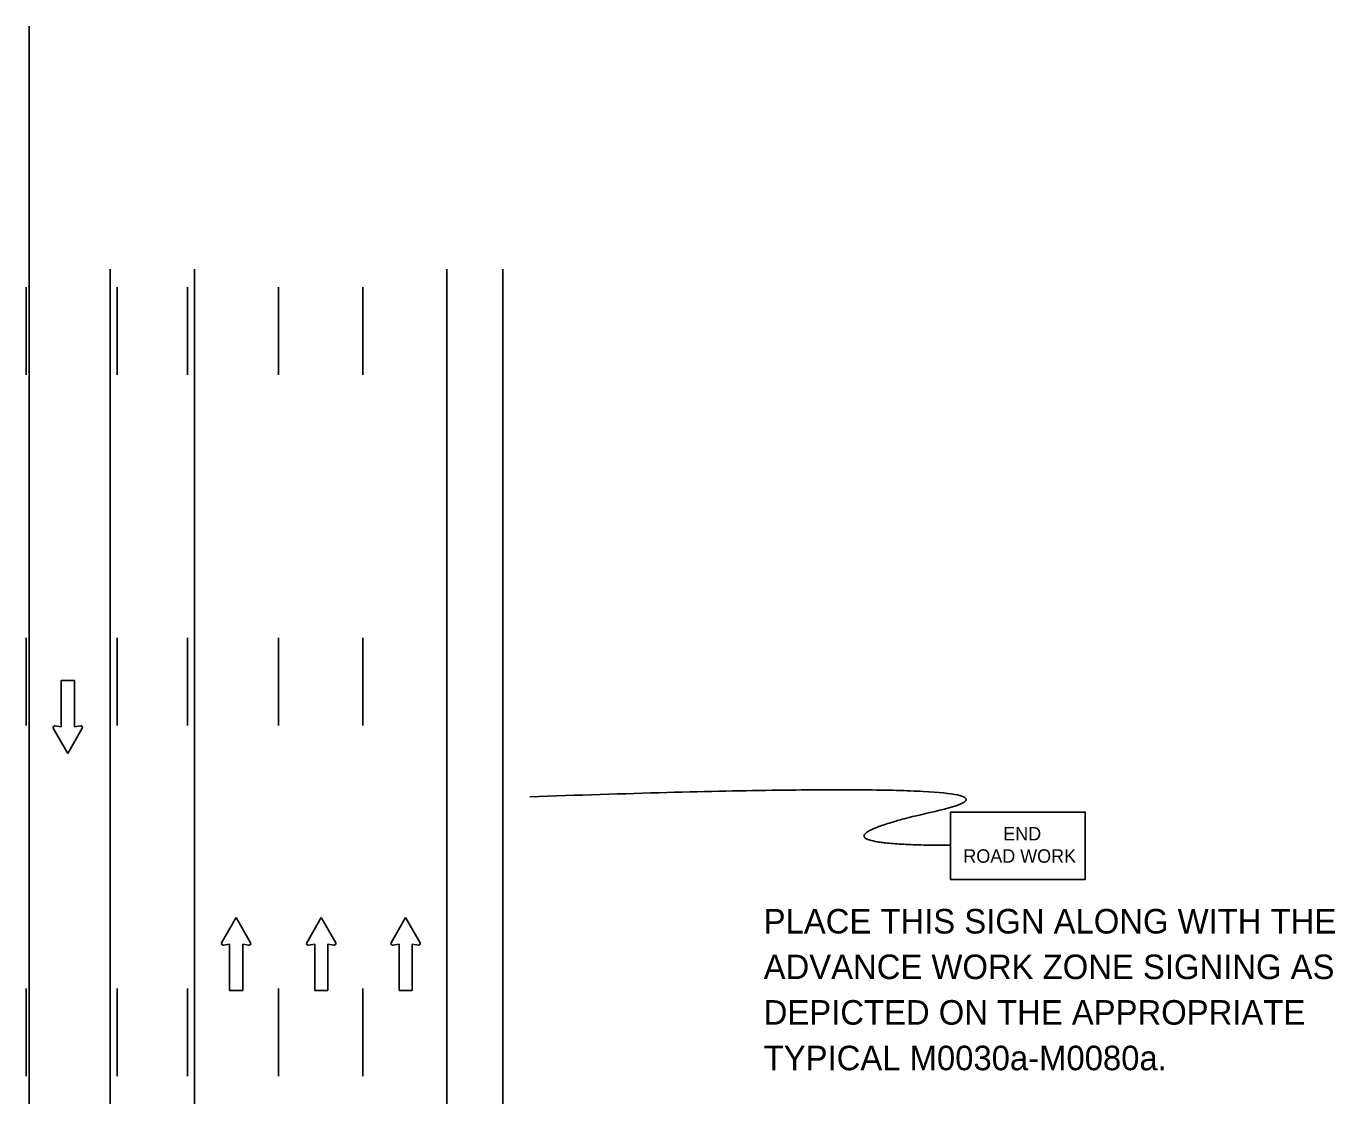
# Model space of a CAD drawing. Extents: x 16038 to 19504, y 5920 to 8321.
# Drawn here: x 17034.3 to 17407.6, y 7975.6 to 8280.7 of the extents above; entities that cross this region are included whole.
import ezdxf

# ---------------------------------------------------------------- set-up
doc = ezdxf.new("R2010")
doc.units = 0
for name, color, linetype in [('ALI_LEGAL_EX', 7, 'Continuous'), ('MT_SCRATCH_LEVEL_E', 7, 'Continuous'), ('PAVT_EDGE_EX', 7, 'Continuous'), ('TRAFFIC_SIGNS_PR', 7, 'Continuous')]:
    doc.layers.add(name, color=color, linetype=linetype)

msp = doc.modelspace()

# ---------------------------------------------------------------- linework, layer by layer
at = {"layer": 'ALI_LEGAL_EX'}
for points in [[(17034.3, 8181.21), (17034.3, 8206.21)], [(17060.3, 8181.21), (17060.3, 8206.21)], [(17080.3, 8181.21), (17080.3, 8206.21)], [(17106.3, 8181.21), (17106.3, 8206.21)], [(17130.3, 8181.21), (17130.3, 8206.21)], [(17034.3, 8081.21), (17034.3, 8106.21)], [(17060.3, 8081.21), (17060.3, 8106.21)], [(17080.3, 8081.21), (17080.3, 8106.21)], [(17106.3, 8081.21), (17106.3, 8106.21)], [(17130.3, 8081.21), (17130.3, 8106.21)], [(17034.3, 7981.21), (17034.3, 8006.21)], [(17060.3, 7981.21), (17060.3, 8006.21)], [(17080.3, 7981.21), (17080.3, 8006.21)], [(17106.3, 7981.21), (17106.3, 8006.21)], [(17130.3, 7981.21), (17130.3, 8006.21)]]:
    msp.add_lwpolyline(points, dxfattribs=at)
at = {"layer": 'MT_SCRATCH_LEVEL_E'}
for p, q in [((17048.04, 8094.07), (17044.3, 8094.07)), ((17044.3, 8094.07), (17044.3, 8080.81)), ((17048.04, 8094.07), (17044.3, 8094.07)), ((17044.3, 8094.07), (17044.3, 8080.81)), ((17048.04, 8094.07), (17044.3, 8094.07)), ((17044.3, 8094.07), (17044.3, 8080.81)), ((17048.04, 8094.07), (17044.3, 8094.07)), ((17044.3, 8094.07), (17044.3, 8080.81)), ((17048.04, 8080.81), (17048.04, 8094.07)), ((17048.04, 8080.81), (17048.04, 8094.07)), ((17048.04, 8080.81), (17048.04, 8094.07)), ((17048.04, 8080.81), (17048.04, 8094.07)), ((17042.04, 8080.44), (17046.19, 8073.2)), ((17042.04, 8080.44), (17046.19, 8073.2)), ((17042.04, 8080.44), (17046.19, 8073.2)), ((17042.04, 8080.44), (17046.19, 8073.2)), ((17044.3, 8080.81), (17042.52, 8081.12)), ((17044.3, 8080.81), (17042.52, 8081.12)), ((17044.3, 8080.81), (17042.52, 8081.12)), ((17044.3, 8080.81), (17042.52, 8081.12)), ((17046.19, 8073.2), (17050.3, 8080.44)), ((17046.19, 8073.2), (17050.3, 8080.44)), ((17046.19, 8073.2), (17050.3, 8080.44)), ((17046.19, 8073.2), (17050.3, 8080.44)), ((17049.82, 8081.12), (17048.04, 8080.81)), ((17049.82, 8081.12), (17048.04, 8080.81)), ((17049.82, 8081.12), (17048.04, 8080.81)), ((17049.82, 8081.12), (17048.04, 8080.81)), ((17094.17, 8026.46), (17090.06, 8019.22)), ((17094.17, 8026.46), (17090.06, 8019.22)), ((17098.32, 8019.22), (17094.17, 8026.46)), ((17098.32, 8019.22), (17094.17, 8026.46)), ((17118.44, 8026.46), (17114.33, 8019.22)), ((17118.44, 8026.46), (17114.33, 8019.22)), ((17122.59, 8019.22), (17118.44, 8026.46)), ((17122.59, 8019.22), (17118.44, 8026.46)), ((17142.51, 8026.46), (17138.4, 8019.22)), ((17142.51, 8026.46), (17138.4, 8019.22)), ((17146.66, 8019.22), (17142.51, 8026.46)), ((17146.66, 8019.22), (17142.51, 8026.46)), ((17090.54, 8018.54), (17092.32, 8018.85)), ((17090.54, 8018.54), (17092.32, 8018.85)), ((17092.32, 8018.85), (17092.32, 8005.6)), ((17092.32, 8018.85), (17092.32, 8005.6)), ((17096.06, 8005.6), (17096.06, 8018.85)), ((17096.06, 8018.85), (17097.84, 8018.54)), ((17096.06, 8005.6), (17096.06, 8018.85)), ((17096.06, 8018.85), (17097.84, 8018.54)), ((17114.81, 8018.54), (17116.59, 8018.85)), ((17114.81, 8018.54), (17116.59, 8018.85)), ((17116.59, 8018.85), (17116.59, 8005.6)), ((17116.59, 8018.85), (17116.59, 8005.6)), ((17120.33, 8005.6), (17120.33, 8018.85)), ((17120.33, 8018.85), (17122.11, 8018.54)), ((17120.33, 8005.6), (17120.33, 8018.85)), ((17120.33, 8018.85), (17122.11, 8018.54)), ((17138.88, 8018.54), (17140.66, 8018.85)), ((17138.88, 8018.54), (17140.66, 8018.85)), ((17140.66, 8018.85), (17140.66, 8005.6)), ((17140.66, 8018.85), (17140.66, 8005.6)), ((17144.4, 8005.6), (17144.4, 8018.85)), ((17144.4, 8018.85), (17146.18, 8018.54)), ((17144.4, 8005.6), (17144.4, 8018.85)), ((17144.4, 8018.85), (17146.18, 8018.54)), ((17092.32, 8005.6), (17096.06, 8005.6)), ((17092.32, 8005.6), (17096.06, 8005.6)), ((17116.59, 8005.6), (17120.33, 8005.6)), ((17116.59, 8005.6), (17120.33, 8005.6)), ((17140.66, 8005.6), (17144.4, 8005.6)), ((17140.66, 8005.6), (17144.4, 8005.6))]:
    msp.add_line(p, q, dxfattribs=at)
for centre, start, end in [((17042.45, 8080.67), 80.0362, 209.7731), ((17042.45, 8080.67), 80.0362, 209.7731), ((17042.45, 8080.67), 80.0362, 209.7731), ((17042.45, 8080.67), 80.0362, 209.7731), ((17049.89, 8080.67), 330.4248, 99.9638), ((17049.89, 8080.67), 330.4248, 99.9638), ((17049.89, 8080.67), 330.4248, 99.9638), ((17049.89, 8080.67), 330.4248, 99.9638), ((17090.47, 8019), 150.4248, 279.9638), ((17090.47, 8019), 150.4248, 279.9638), ((17097.91, 8019), 260.0362, 29.7731), ((17097.91, 8019), 260.0362, 29.7731), ((17114.74, 8019), 150.4248, 279.9638), ((17114.74, 8019), 150.4248, 279.9638), ((17122.18, 8019), 260.0362, 29.7731), ((17122.18, 8019), 260.0362, 29.7731), ((17138.81, 8019), 150.4248, 279.9638), ((17138.81, 8019), 150.4248, 279.9638), ((17146.25, 8019), 260.0362, 29.7731), ((17146.25, 8019), 260.0362, 29.7731)]:
    msp.add_arc(centre, 0.463, start, end, dxfattribs=at)
at = {"layer": 'PAVT_EDGE_EX'}
for p, q in [((17035.15, 8280.7), (17035.15, 7451.51)), ((17058.3, 8211.37), (17058.3, 7897.34)), ((17082.3, 8211.37), (17082.3, 7923.86)), ((17154.3, 8211.37), (17154.3, 7379.53)), ((17170.3, 8211.37), (17170.3, 7379.53))]:
    msp.add_line(p, q, dxfattribs=at)
at = {"layer": 'TRAFFIC_SIGNS_PR'}
msp.add_lwpolyline([(17298, 8037.31), (17336.4, 8037.31), (17336.4, 8056.51), (17298, 8056.51)], close=True, dxfattribs=at)
msp.add_open_spline([(17298.15, 8047.03), (17250.92, 8047.03), (17335.94, 8066.38), (17177.98, 8060.89)], degree=2, dxfattribs=at)

# ---------------------------------------------------------------- texts
for s, height, p in [('END', 3.831, (17313, 8048.44)), ('ROAD WORK', 3.831, (17301.61, 8042.06)), ('PLACE THIS SIGN ALONG WITH THE', 7, (17244.67, 8021.87)), ('ADVANCE WORK ZONE SIGNING AS', 7, (17244.67, 8008.87)), ('DEPICTED ON THE APPROPRIATE', 7, (17244.67, 7995.87)), ('TYPICAL M0030a-M0080a.', 7, (17244.67, 7982.87))]:
    msp.add_text(s, height=height, dxfattribs=at).set_placement(p)

doc.saveas('drawing.dxf')
